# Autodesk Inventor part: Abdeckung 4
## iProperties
Shininess: 64.0
Length Units: 11269
Angle Units: 11279
Time Units: 11290
Mass Units: 11283
Length Display Precision: 3
Angle Display Precision: 2
Compacted: True
Part Number: Abdeckung 4
Document SubType Name: Sheet Metal
Created: 2005-02
Material: Nichtrostender Stahl (austenitisch)
Designer: Administrator
Manufacturer: Standard
Standards Organization: Custom
Density: 0.0
Volumn: 0.0
Area: 0.0
PropertySet Name: Model Information
Control State: 0
Master: False
Checked Out: False
Author: Administrator
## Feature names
1. Platte1
2. Platte2
3. Biegung1
4. Platte3
5. Biegung2
6. Platte4
7. Biegung3
8. Platte5
9. Biegung4
10. Platte6
11. Biegung5
12. Platte7
13. Biegung6
14. Platte8
15. Biegung7
16. Platte9
17. Biegung8
18. ExtrusionAbwicklung1
19. Ecke1
20. Ecke2
21. Ecke3
22. Ecke4
23. Ausklinkung1
24. Ecke5
25. Ecke6
26. Ecke7
27. Ausklinkung2
28. Ausklinkung3
